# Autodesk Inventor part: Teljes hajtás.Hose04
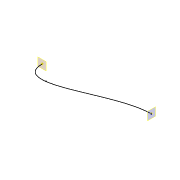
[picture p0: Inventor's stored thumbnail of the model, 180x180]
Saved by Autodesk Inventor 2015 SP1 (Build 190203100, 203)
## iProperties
_PSKETCH_SNAP: False
_PSKETCH_RSNP: False
_BASENETWORK_NOTAUTODIMENSION: False
StyleName: _Piping Style 20
Created: 2013-02
Part Number: Teljes hajtás.Hose04
Material: Generic
Document SubType Name: Modeling
Designer: Marci
Density: 1 g/cm^3
Appearance: Default
ActiveState: True
Angle: UnInitValue
BendRadius: 0.500 in
CouplingKey: UnInitValue
DefaultBendRadius: UnInitValue
Diameter: 1/4
DiameterType: Nominal
Elbow45Key: UnInitValue
Elbow90Key: UnInitValue
ElbowCustomKey: UnInitValue
Ending: UnInitValue
FittingMaterial: UnInitValue
FittingStandard: UnInitValue
FlangeKey: UnInitValue
Gap: UnInitValue
GasketKey: UnInitValue
ID: 0,635
IsButtWelded: UnInitValue
IsFlanged: UnInitValue
IsSelfDraining: UnInitValue
Material: UnInitValue
MixedUnits: UnInitValue
Name: Hydraulic Hose - No Fittings
OD: 1,4986
PipeKey: v3#d489867e-ac9b-47ea-b952-0a1b885f66be#1
PipeType: Flexible Hose
PipingComponentColor: Blue - Wall Paint - Glossy
RoundUpValue: 0.125 in
RouteDirection45: UnInitValue
RouteDirection90: UnInitValue
Schedule: ID=0.25
ShowGap: UnInitValue
Standard: UnInitValue
SuppressEndFitting: True
SuppressStartFitting: True
UseFlangsForCouplings: UnInitValue
UseSubASM: True
_ComponentInfo: <CS><C N="Pipe" R="0,749300" OR="0,749300" IR="0,317500" PL="PL" PartType="pipe" SymKey="" PN="Parker hidraulikatömlő - No Skive 1/4"><CO N="1"><FE V="0"/><FD V
Author: Marci
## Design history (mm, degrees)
workpoint "Work Point1"
workplane "Work Plane1"
workpoint "Work Point2"
workplane "Work Plane2"
sketch "3D Sketch1" dims "d0" = 10, "d1" = 0.1 (derived), "d2" = 10, "d3" = 0.1 (derived)
other parameters: "B" = 12.7 [user parameter]
